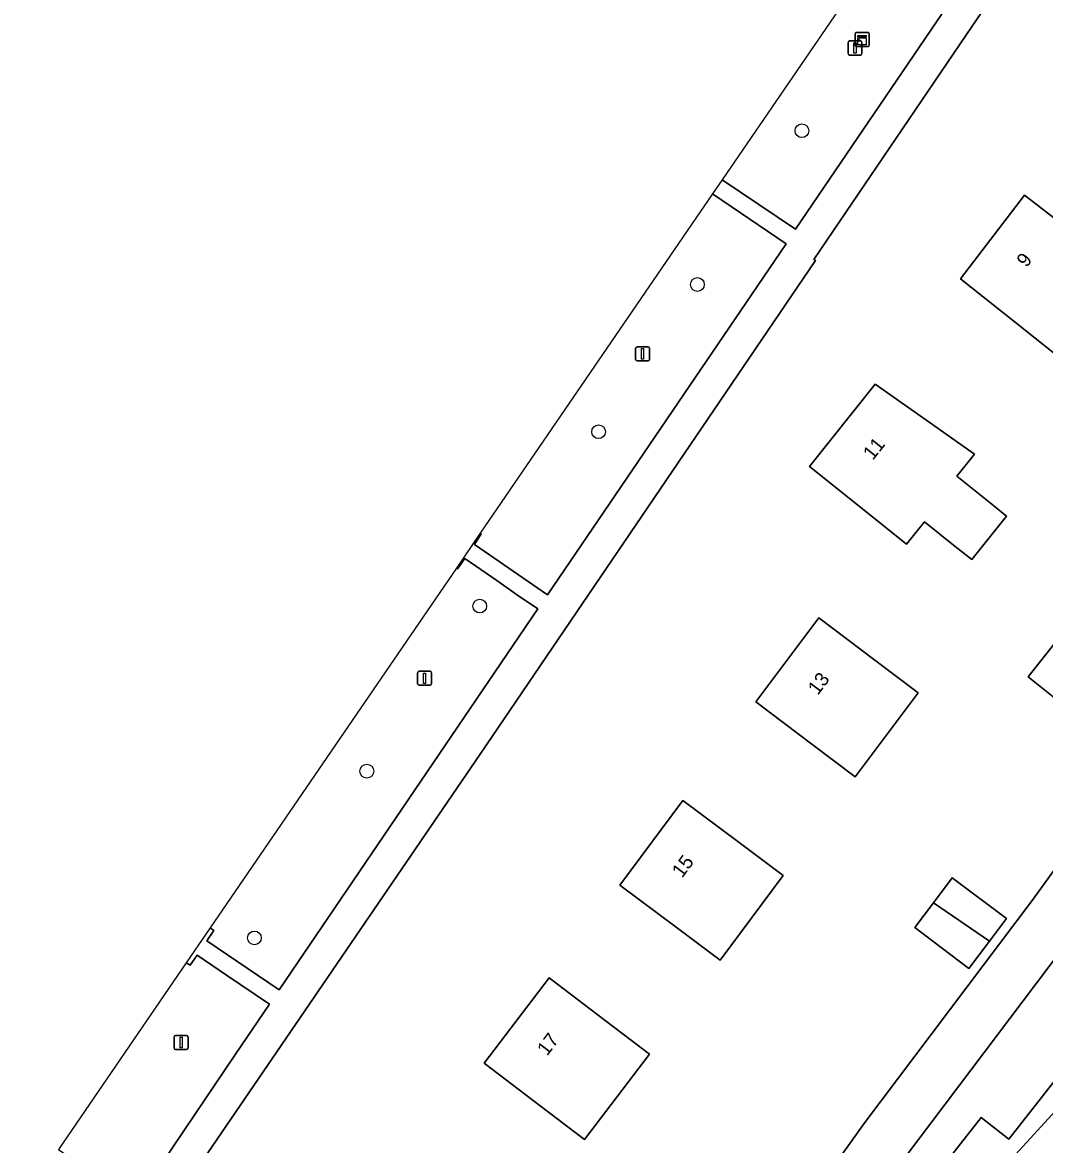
# Model space of a CAD drawing. Extents: x 158793 to 159888, y 384317 to 385256.
# Drawn here: x 159078.9 to 159151.7, y 385000.3 to 385080.3 of the extents above; entities that cross this region are included whole.
import ezdxf

# ---------------------------------------------------------------- set-up
doc = ezdxf.new("R2010")
doc.units = 0
for name, color, linetype in [('IMGEO_Berm_groen', 7, 'Continuous'), ('IMGEO_Boom', 7, 'Continuous'), ('IMGEO_Erf', 7, 'Continuous'), ('IMGEO_Groenvoorziening', 7, 'Continuous'), ('IMGEO_Hek', 7, 'Continuous'), ('IMGEO_Kast', 7, 'Continuous'), ('IMGEO_Lichtmast', 7, 'Continuous'), ('IMGEO_Pand', 7, 'Continuous'), ('IMGEO_Pand_nummerreeks', 7, 'Continuous'), ('IMGEO_Parkeervlak_open', 7, 'Continuous'), ('IMGEO_Rijbaan_lokaal_open', 7, 'Continuous'), ('IMGEO_Voetpad_open', 7, 'Continuous')]:
    doc.layers.add(name, color=color, linetype=linetype)

msp = doc.modelspace()

# ---------------------------------------------------------------- linework, layer by layer
at = {"layer": 'IMGEO_Berm_groen'}
for points in [[(159128.769, 385069.054), (159133.999, 385065.519), (159144.839, 385081.483), (159147.728, 385085.71), (159150.174, 385089.261), (159145.022, 385092.804)], [(159111.544, 385043.883), (159111.615, 385043.835), (159111.128, 385043.073), (159116.322, 385039.492), (159133.316, 385064.48), (159128.083, 385068.051)], [(159092.304, 385015.767), (159092.584, 385015.582), (159092.088, 385014.853), (159097.226, 385011.36), (159115.644, 385038.496), (159114.127, 385039.508), (159112.719, 385040.516), (159110.446, 385042.074), (159109.934, 385041.339), (159109.844, 385041.399)], [(159081.505, 384999.986), (159084.758, 384997.737), (159078.948, 384989.428), (159080.124, 384988.626), (159082.915, 384986.948), (159089.625, 384996.759), (159088.962, 384999.139), (159094.107, 385006.771), (159096.534, 385010.341), (159093.469, 385012.397), (159091.377, 385013.835), (159090.881, 385013.109), (159090.611, 385013.292)]]:
    msp.add_lwpolyline(points, close=True, dxfattribs=at)
at = {"layer": 'IMGEO_Boom'}
for centre in [(159134.454, 385072.539), (159127.01, 385061.59), (159119.974, 385051.109), (159111.509, 385038.687), (159103.468, 385026.934), (159095.468, 385015.062)]:
    msp.add_circle(centre, 0.489, dxfattribs=at)
at = {"layer": 'IMGEO_Erf'}
for points in [[(159148.394, 384946.912), (159153.251, 384941.028), (159150.399, 384957.609), (159141, 384963.539), (159137.019, 384980.94), (159133.839, 384985.25), (159147.589, 384997.369), (159157.45, 385008.13), (159161.829, 385013.789), (159170.019, 385025.489), (159207.92, 385081.38), (159212.01, 385087.95), (159216.48, 385096.14), (159221.549, 385107.19), (159187.72, 385129.9), (159183.535, 385132.814), (159182.116, 385130.797), (159173.31, 385118.352), (159168.14, 385111.045), (159165.803, 385107.726)], [(159151.5, 385087.223), (159146.569, 385079.985), (159135.306, 385063.376), (159135.41, 385063.302), (159118.837, 385038.88), (159111.535, 385028.137), (159091.494, 384998.786), (159092.362, 384995.835), (159103.204, 384987.734), (159110.076, 384982.302), (159117.408, 384976.04), (159118.4, 384977.13), (159120.786, 384975), (159124.18, 384971.909), (159124.279, 384971.818), (159127.169, 384969.189), (159127.349, 384969.38), (159127.296, 384969.43), (159129.774, 384972.033), (159131.929, 384969.989), (159129.462, 384967.367), (159129.341, 384967.231), (159131.486, 384965.091)], [(159158.881, 385044.068), (159160.964, 385046.67), (159165.713, 385042.868), (159167.168, 385044.684), (159171.397, 385049.958), (159174.131, 385047.766), (159176.866, 385045.573), (159179.6, 385043.381), (159175.37, 385038.106), (159177.289, 385036.566), (159149.19, 385000.73), (159147.215, 385002.279), (159137.859, 384990.346), (159134.343, 384989.569), (159134.223, 384989.269), (159133.37, 384986.164), (159133.366, 384984.555), (159138.027, 384965.838), (159146.931, 384955.339), (159147.464, 384954.685)], [(159143.646, 384954.591), (159135.618, 384964.166), (159131.968, 384977.645), (159130.802, 384982.659), (159130.621, 384989.574), (159132.728, 384993.243), (159138.932, 385001.917), (159150.926, 385017.823), (159158.018, 385027.678), (159155.296, 385029.857), (159150.547, 385033.659), (159152.631, 385036.262), (159154.714, 385038.864), (159156.798, 385041.466), (159158.881, 385044.068)]]:
    msp.add_lwpolyline(points, dxfattribs=at)
for points in [[(159149.646, 385058.895), (159145.729, 385062.003), (159150.296, 385067.943), (159154.26, 385064.895), (159157.216, 385062.621), (159152.46, 385056.663)], [(159145.484, 385047.93), (159147.849, 385046.035), (159149.023, 385045.095), (159146.541, 385041.998), (159145.367, 385042.938), (159143.175, 385044.694), (159141.893, 385043.095), (159138.879, 385045.509), (159134.977, 385048.636), (159139.67, 385054.493), (159143.755, 385051.61), (159146.742, 385049.501)], [(159138.24, 385026.54), (159135.153, 385028.862), (159131.156, 385031.867), (159135.648, 385037.841), (159139.645, 385034.836), (159142.732, 385032.514)], [(159133.12, 385019.506), (159128.621, 385013.483), (159125.487, 385015.825), (159121.481, 385018.817), (159125.98, 385024.84), (159129.986, 385021.848)], [(159149.016, 385016.43), (159147.801, 385014.82), (159146.34, 385012.885), (159142.478, 385015.8), (159143.81, 385017.566), (159145.153, 385019.345)], [(159120.428, 385009.181), (159123.592, 385006.771), (159118.969, 385000.701), (159115.805, 385003.111), (159111.828, 385006.141), (159116.451, 385012.211)]]:
    msp.add_lwpolyline(points, close=True, dxfattribs=at)
at = {"layer": 'IMGEO_Groenvoorziening'}
msp.add_lwpolyline([(159273.06, 385209.092), (159256.152, 385207.464), (159235.717, 385186.968), (159227.01, 385178.109), (159209.26, 385158.099), (159192.739, 385136.789), (159187.72, 385129.9), (159221.549, 385107.19), (159216.48, 385096.14), (159212.01, 385087.95), (159207.92, 385081.38), (159170.019, 385025.489), (159161.829, 385013.789), (159157.45, 385008.13), (159147.589, 384997.369), (159133.839, 384985.25), (159137.019, 384980.94), (159141, 384963.539), (159150.399, 384957.609), (159153.251, 384941.028), (159155.132, 384938.749), (159161.811, 384930.659), (159170.007, 384919.816)], dxfattribs=at)
at = {"layer": 'IMGEO_Hek'}
msp.add_lwpolyline([(159153.359, 384941.51), (159150.399, 384957.609), (159141, 384963.539), (159137.019, 384980.94), (159133.839, 384985.25), (159147.589, 384997.369), (159157.45, 385008.13), (159161.829, 385013.789), (159170.019, 385025.489), (159207.92, 385081.38), (159212.01, 385087.95), (159216.48, 385096.14), (159221.549, 385107.19), (159187.72, 385129.9), (159192.739, 385136.789), (159209.26, 385158.099), (159227.01, 385178.109), (159235.717, 385186.968)], dxfattribs=at)
at = {"layer": 'IMGEO_Kast'}
for p, q in [((159138.238, 385078.609), (159138.238, 385079.45)), ((159138.238, 385079.45), (159138.238, 385078.609)), ((159138.313, 385079.534), (159139.154, 385079.534)), ((159139.154, 385079.534), (159138.313, 385079.534)), ((159139.238, 385079.459), (159139.238, 385078.618)), ((159139.238, 385078.618), (159139.238, 385079.459)), ((159139.163, 385078.534), (159138.322, 385078.534)), ((159138.322, 385078.534), (159139.163, 385078.534))]:
    msp.add_line(p, q, dxfattribs=at)
for points in [[(159138.433, 385079.324), (159139.033, 385079.324), (159139.033, 385079.239), (159138.433, 385079.239), (159138.433, 385079.324)], [(159138.433, 385079.149), (159139.033, 385079.149), (159139.033, 385078.66), (159138.433, 385078.66), (159138.433, 385079.149)]]:
    msp.add_lwpolyline(points, dxfattribs=at)
msp.add_circle((159138.517, 385078.998), 0.0377, dxfattribs=at)
for centre, start, end in [((159138.316, 385079.456), 92.4484, 184.28452), ((159138.316, 385079.456), 92.4484, 184.28452), ((159139.16, 385079.456), 2.4484, 94.28452), ((159139.16, 385079.456), 2.4484, 94.28452), ((159138.316, 385078.612), 182.4484, 274.28452), ((159138.316, 385078.612), 182.4484, 274.28452), ((159139.16, 385078.612), 272.4484, 4.28452), ((159139.16, 385078.612), 272.4484, 4.28452)]:
    msp.add_arc(centre, 0.0779, start, end, dxfattribs=at)
at = {"layer": 'IMGEO_Lichtmast'}
for p, q in [((159137.731, 385078.032), (159137.731, 385078.832)), ((159137.731, 385078.832), (159137.731, 385078.032)), ((159137.831, 385078.932), (159138.621, 385078.932)), ((159138.621, 385078.932), (159137.831, 385078.932)), ((159138.721, 385078.832), (159138.721, 385078.032)), ((159138.721, 385078.032), (159138.721, 385078.832)), ((159138.621, 385077.932), (159137.831, 385077.932)), ((159137.831, 385077.932), (159138.621, 385077.932)), ((159122.608, 385056.246), (159122.608, 385057.046)), ((159122.608, 385057.046), (159122.608, 385056.246)), ((159122.708, 385057.146), (159123.498, 385057.146)), ((159123.498, 385057.146), (159122.708, 385057.146)), ((159123.598, 385057.046), (159123.598, 385056.246)), ((159123.598, 385056.246), (159123.598, 385057.046)), ((159123.498, 385056.146), (159122.708, 385056.146)), ((159122.708, 385056.146), (159123.498, 385056.146)), ((159107.085, 385033.147), (159107.085, 385033.947)), ((159107.085, 385033.947), (159107.085, 385033.147)), ((159107.185, 385034.047), (159107.975, 385034.047)), ((159107.975, 385034.047), (159107.185, 385034.047)), ((159108.075, 385033.947), (159108.075, 385033.147)), ((159108.075, 385033.147), (159108.075, 385033.947)), ((159107.975, 385033.047), (159107.185, 385033.047)), ((159107.185, 385033.047), (159107.975, 385033.047)), ((159089.748, 385007.218), (159089.748, 385008.018)), ((159089.748, 385008.018), (159089.748, 385007.218)), ((159089.848, 385008.118), (159090.638, 385008.118)), ((159090.638, 385008.118), (159089.848, 385008.118)), ((159090.738, 385008.018), (159090.738, 385007.218)), ((159090.738, 385007.218), (159090.738, 385008.018)), ((159090.638, 385007.118), (159089.848, 385007.118)), ((159089.848, 385007.118), (159090.638, 385007.118))]:
    msp.add_line(p, q, dxfattribs=at)
for points in [[(159138.151, 385078.807), (159138.301, 385078.807), (159138.301, 385078.057), (159138.151, 385078.057), (159138.151, 385078.807)], [(159123.028, 385057.021), (159123.178, 385057.021), (159123.178, 385056.271), (159123.028, 385056.271), (159123.028, 385057.021)], [(159107.505, 385033.922), (159107.655, 385033.922), (159107.655, 385033.172), (159107.505, 385033.172), (159107.505, 385033.922)], [(159090.168, 385007.993), (159090.318, 385007.993), (159090.318, 385007.243), (159090.168, 385007.243), (159090.168, 385007.993)]]:
    msp.add_lwpolyline(points, dxfattribs=at)
for centre, start, end in [((159137.831, 385078.832), 90, 180), ((159137.831, 385078.832), 90, 180), ((159138.621, 385078.832), 0, 90), ((159138.621, 385078.832), 360, 90), ((159137.831, 385078.032), 180, 270), ((159137.831, 385078.032), 180, 270), ((159138.621, 385078.032), 270, 0), ((159138.621, 385078.032), 270, 0), ((159122.708, 385057.046), 90, 180), ((159122.708, 385057.046), 90, 180), ((159123.498, 385057.046), 0, 90), ((159123.498, 385057.046), 360, 90), ((159122.708, 385056.246), 180, 270), ((159122.708, 385056.246), 180, 270), ((159123.498, 385056.246), 270, 0), ((159123.498, 385056.246), 270, 0), ((159107.185, 385033.947), 90, 180), ((159107.185, 385033.947), 90, 180), ((159107.975, 385033.947), 0, 90), ((159107.975, 385033.947), 360, 90), ((159107.185, 385033.147), 180, 270), ((159107.185, 385033.147), 180, 270), ((159107.975, 385033.147), 270, 0), ((159107.975, 385033.147), 270, 0), ((159089.848, 385008.018), 90, 180), ((159089.848, 385008.018), 90, 180), ((159090.638, 385008.018), 0, 90), ((159090.638, 385008.018), 360, 90), ((159089.848, 385007.218), 180, 270), ((159089.848, 385007.218), 180, 270), ((159090.638, 385007.218), 270, 0), ((159090.638, 385007.218), 270, 0)]:
    msp.add_arc(centre, 0.1, start, end, dxfattribs=at)
at = {"layer": 'IMGEO_Pand'}
for points in [[(159149.646, 385058.895), (159152.46, 385056.663), (159157.216, 385062.621), (159154.26, 385064.895), (159150.296, 385067.943), (159145.729, 385062.003)], [(159146.742, 385049.501), (159143.755, 385051.61), (159139.67, 385054.493), (159134.977, 385048.636), (159138.879, 385045.509), (159141.893, 385043.095), (159143.175, 385044.694), (159145.367, 385042.938), (159146.541, 385041.998), (159149.023, 385045.095), (159147.849, 385046.035), (159145.484, 385047.93)], [(159135.153, 385028.862), (159138.24, 385026.54), (159142.732, 385032.514), (159139.645, 385034.836), (159135.648, 385037.841), (159131.156, 385031.867)], [(159152.631, 385036.262), (159150.547, 385033.659), (159155.296, 385029.857), (159157.38, 385032.459)], [(159129.986, 385021.848), (159125.98, 385024.84), (159121.481, 385018.817), (159125.487, 385015.825), (159128.621, 385013.483), (159133.12, 385019.506)], [(159147.801, 385014.82), (159149.016, 385016.43), (159145.153, 385019.345), (159143.81, 385017.566)], [(159147.801, 385014.82), (159143.81, 385017.566), (159142.478, 385015.8), (159146.34, 385012.885)], [(159120.428, 385009.181), (159116.451, 385012.211), (159111.828, 385006.141), (159115.805, 385003.111), (159118.969, 385000.701), (159123.592, 385006.771)]]:
    msp.add_lwpolyline(points, close=True, dxfattribs=at)
at = {"layer": 'IMGEO_Parkeervlak_open'}
msp.add_lwpolyline([(159177.289, 385036.566), (159175.37, 385038.106), (159172.636, 385040.299), (159134.343, 384989.569), (159137.859, 384990.346), (159147.215, 385002.279), (159149.19, 385000.73)], close=True, dxfattribs=at)
at = {"layer": 'IMGEO_Rijbaan_lokaal_open'}
for points in [[(159172.636, 385040.299), (159169.902, 385042.491), (159167.168, 385044.684), (159165.713, 385042.868), (159163.63, 385040.266), (159161.546, 385037.664), (159159.463, 385035.062), (159157.38, 385032.459), (159155.296, 385029.857), (159158.018, 385027.678), (159150.926, 385017.823), (159138.932, 385001.917), (159132.728, 384993.243), (159130.621, 384989.574), (159130.802, 384982.659), (159131.968, 384977.645), (159135.618, 384964.166), (159143.646, 384954.591)], [(159147.464, 384954.685), (159146.931, 384955.339), (159138.027, 384965.838), (159133.366, 384984.555), (159133.37, 384986.164), (159134.223, 384989.269), (159134.343, 384989.569), (159172.636, 385040.299)]]:
    msp.add_lwpolyline(points, dxfattribs=at)
at = {"layer": 'IMGEO_Voetpad_open'}
for points in [[(159131.486, 384965.091), (159129.341, 384967.231), (159129.462, 384967.367), (159127.349, 384969.38), (159127.169, 384969.189), (159124.279, 384971.818), (159124.18, 384971.909), (159120.786, 384975), (159118.4, 384977.13), (159117.408, 384976.04), (159110.076, 384982.302), (159103.204, 384987.734), (159092.362, 384995.835), (159091.494, 384998.786), (159111.535, 385028.137), (159118.837, 385038.88), (159135.41, 385063.302), (159135.306, 385063.376), (159146.569, 385079.985), (159151.5, 385087.223)], [(159144.839, 385081.483), (159133.999, 385065.519), (159128.769, 385069.054), (159128.083, 385068.051), (159133.316, 385064.48), (159116.322, 385039.492), (159111.128, 385043.073), (159111.615, 385043.835), (159111.544, 385043.883), (159109.844, 385041.399), (159109.934, 385041.339), (159110.446, 385042.074), (159112.719, 385040.516), (159114.127, 385039.508), (159115.644, 385038.496), (159097.226, 385011.36), (159092.088, 385014.853), (159092.584, 385015.582), (159092.304, 385015.767), (159090.611, 385013.292)], [(159090.611, 385013.292), (159090.881, 385013.109), (159091.377, 385013.835), (159093.469, 385012.397), (159096.534, 385010.341), (159094.107, 385006.771), (159088.962, 384999.139), (159089.625, 384996.759), (159090.266, 384994.46), (159095.671, 384990.269), (159099.989, 384987.088), (159104.507, 384983.566), (159111.287, 384978.016), (159117.659, 384972.637), (159118.512, 384973.602), (159121.007, 384971.505)]]:
    msp.add_lwpolyline(points, dxfattribs=at)

# ---------------------------------------------------------------- texts
at = {"layer": 'IMGEO_Pand_nummerreeks'}
for s, rotation, p in [('9', 52.44493, (159150.445, 385062.755)), ('11', 51.29691, (159139.495, 385049.029)), ('13', 53.05958, (159135.582, 385032.295)), ('15', 53.24138, (159125.918, 385019.277)), ('17', 52.70658, (159116.304, 385006.604))]:
    msp.add_text(s, height=1, rotation=rotation, dxfattribs=at).set_placement(p)

doc.saveas('drawing.dxf')
